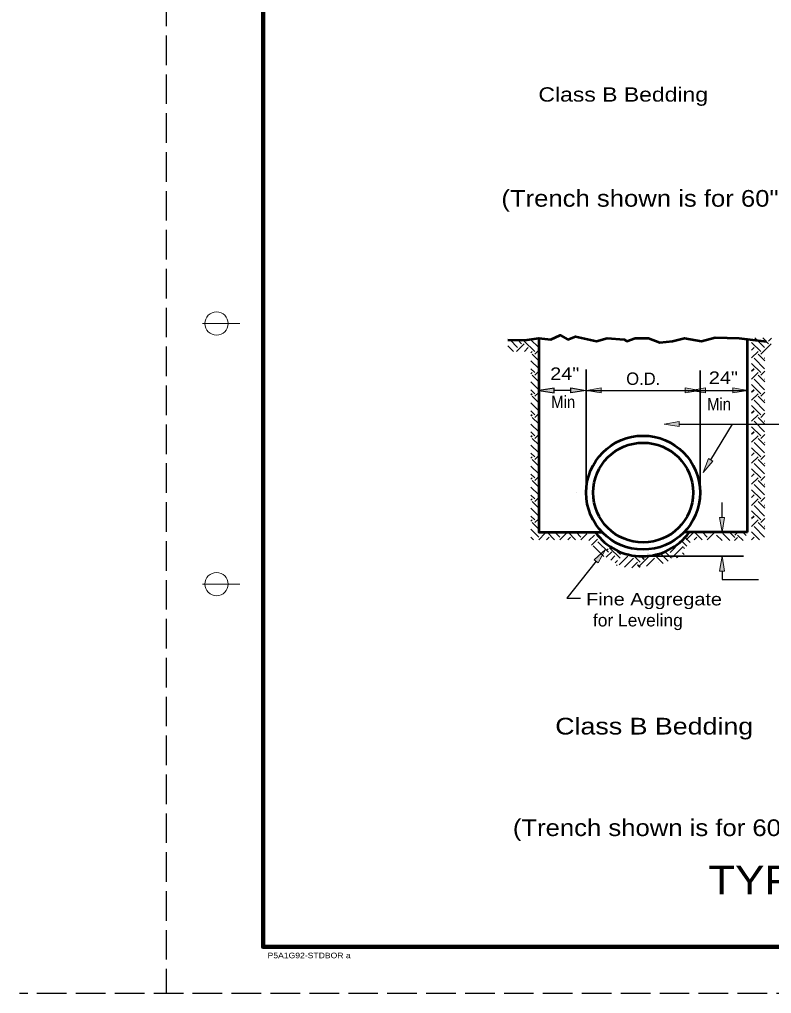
# Model space of a CAD drawing. Extents: x 36.1 to 71.5, y 0.2 to 22.2.
# Drawn here: x 36.14 to 44.21, y 0.21 to 10.68 of the extents above; entities that cross this region are included whole.
import ezdxf

# ---------------------------------------------------------------- set-up
doc = ezdxf.new("R2010")
doc.units = 0
doc.header["$LTSCALE"] = 0.053
doc.header["$PDMODE"] = 32
doc.header["$PDSIZE"] = 0.0265
doc.linetypes.add('LONG_DASHED', pattern=[7.5, 6, -1.5])
for name, color, linetype, lineweight in [('1', 7, 'Continuous', 35), ('3', 7, 'Continuous', 25), ('4', 7, 'Continuous', 35), ('6', 7, 'Continuous', 13)]:
    doc.layers.add(name, color=color, linetype=linetype, lineweight=lineweight)

msp = doc.modelspace()

# ---------------------------------------------------------------- hatches: boundary and pattern name
at = {"layer": '1'}
for points in [[(41.87908, 6.66708), (41.87908, 6.72042), (41.71908, 6.69375), (41.71908, 6.69375)], [(42.05908, 6.66875), (42.05908, 6.72208), (42.21908, 6.69542), (42.21908, 6.69542)], [(42.38567, 6.66733), (42.38567, 6.72075), (42.22567, 6.69408), (42.22567, 6.69408)], [(43.28842, 6.66733), (43.28842, 6.72075), (43.44842, 6.69408), (43.44842, 6.69408)]]:
    msp.add_hatch(color=256, dxfattribs=at).paths.add_polyline_path(points)
at = {"layer": '3'}
for points in [[(43.50392, 6.66858), (43.50392, 6.72192), (43.34392, 6.69525), (43.34392, 6.69525)], [(43.80058, 6.66858), (43.80058, 6.72192), (43.96058, 6.69525), (43.96058, 6.69525)], [(43.22292, 6.30617), (43.22292, 6.35942), (43.06292, 6.33283), (43.06292, 6.33283)], [(43.58492, 5.93458), (43.53925, 5.96217), (43.4795, 5.81133), (43.4795, 5.81133)], [(43.71075, 5.3305), (43.65742, 5.3305), (43.68408, 5.1705), (43.68408, 5.1705)], [(42.31042, 4.87483), (42.35225, 4.84158), (42.43058, 4.98367), (42.43058, 4.98367)], [(43.71075, 4.75192), (43.65742, 4.75192), (43.68408, 4.91192), (43.68408, 4.91192)]]:
    msp.add_hatch(color=256, dxfattribs=at).paths.add_polyline_path(points)

# ---------------------------------------------------------------- linework, layer by layer
at = {"layer": '1', "linetype": 'LONG_DASHED', "lineweight": 25}
for p, q in [((37.71217, 22.21317), (37.71217, 0.21317)), ((71.33717, 0.21317), (36.13717, 0.21317))]:
    msp.add_line(p, q, dxfattribs=at)
at = {"layer": '1', "lineweight": 158}
msp.add_line((38.75383, 21.71317), (38.75383, 0.71317), dxfattribs=at)
at = {"layer": '1', "lineweight": 13}
for p, q in [((38.50383, 7.41317), (38.10383, 7.41317)), ((43.61867, 5.1705), (43.45367, 5.1705)), ((38.50383, 4.61317), (38.10383, 4.61317))]:
    msp.add_line(p, q, dxfattribs=at)
at = {"layer": '1', "lineweight": 53}
for q in [(43.95658, 7.2445), (43.27125, 5.1705)]:
    msp.add_line((43.95658, 5.1705), q, dxfattribs=at)
at = {"layer": '1'}
for p, q in [((42.22408, 5.67058), (42.22408, 6.91892)), ((43.44833, 5.65942), (43.44833, 6.90775))]:
    msp.add_line(p, q, dxfattribs=at)
at = {"layer": '1', "lineweight": 25}
for p, q in [((42.06375, 6.69375), (41.88033, 6.69375)), ((42.2295, 6.69408), (43.44833, 6.69408))]:
    msp.add_line(p, q, dxfattribs=at)
at = {"layer": '1', "lineweight": 158}
msp.add_lwpolyline([(71.25383, 21.71317), (71.25383, 0.71317), (38.75383, 0.71317)], dxfattribs=at)
at = {"layer": '1', "lineweight": 53}
for points in [[(41.38342, 7.23725), (41.56667, 7.23458), (41.71408, 7.25475), (41.71408, 5.1705), (42.3945, 5.1705)], [(41.71408, 7.25475), (41.84458, 7.24108), (41.94267, 7.28867), (42.02575, 7.24108), (42.10892, 7.27275), (42.3355, 7.22517), (42.44892, 7.25683), (42.63025, 7.24108), (42.66042, 7.22517), (42.75108, 7.25683), (42.89467, 7.25683), (43.0155, 7.20925), (43.1515, 7.22517), (43.27992, 7.25683), (43.46125, 7.22517), (43.61083, 7.2615)], [(43.61083, 7.2615), (43.86717, 7.25475), (44.16192, 7.22117)]]:
    msp.add_lwpolyline(points, dxfattribs=at)
at = {"layer": '1', "lineweight": 25}
for points in [[(41.87908, 6.66708), (41.87908, 6.72042), (41.71908, 6.69375), (41.71908, 6.69375)], [(42.05908, 6.66875), (42.05908, 6.72208), (42.21908, 6.69542), (42.21908, 6.69542)]]:
    msp.add_lwpolyline(points, close=True, dxfattribs=at)
at = {"layer": '1', "lineweight": 13}
for points in [[(42.38567, 6.66733), (42.38567, 6.72075), (42.22567, 6.69408), (42.22567, 6.69408)], [(43.28842, 6.66733), (43.28842, 6.72075), (43.44842, 6.69408), (43.44842, 6.69408)]]:
    msp.add_lwpolyline(points, close=True, dxfattribs=at)
for centre in [(38.25383, 7.41317), (38.25383, 4.61317)]:
    msp.add_circle(centre, 0.125, dxfattribs=at)
at = {"layer": '1', "lineweight": 53}
for radius in [0.61202, 0.53646]:
    msp.add_circle((42.83535, 5.59617), radius, dxfattribs=at)
msp.add_arc((42.82617, 5.53271), 0.6208, 215.70389, 324.29611, dxfattribs=at)
at = {"layer": '1'}
msp.add_point((38.75383, 0.71317), dxfattribs=at)
at = {"layer": '3'}
for p, q in [((43.348, 6.69458), (43.95658, 6.69458)), ((43.22292, 6.33283), (44.53925, 6.33283)), ((43.56208, 5.94842), (43.79375, 6.33283)), ((43.68408, 5.3305), (43.68408, 5.4905)), ((43.68408, 4.75192), (43.68408, 4.661)), ((43.68408, 4.661), (44.07525, 4.661))]:
    msp.add_line(p, q, dxfattribs=at)
at = {"layer": '3', "lineweight": 13}
for p, q in [((43.61083, 6.68608), (43.61092, 6.68608)), ((43.68408, 4.91192), (43.68425, 4.91192))]:
    msp.add_line(p, q, dxfattribs=at)
at = {"layer": '3', "lineweight": 35}
msp.add_line((42.80025, 4.91192), (43.9145, 4.91192), dxfattribs=at)
at = {"layer": '3', "lineweight": 13}
for points in [[(43.50392, 6.66858), (43.50392, 6.72192), (43.34392, 6.69525), (43.34392, 6.69525)], [(43.80058, 6.66858), (43.80058, 6.72192), (43.96058, 6.69525), (43.96058, 6.69525)], [(43.22292, 6.30617), (43.22292, 6.35942), (43.06292, 6.33283), (43.06292, 6.33283)], [(43.58492, 5.93458), (43.53925, 5.96217), (43.4795, 5.81133), (43.4795, 5.81133)], [(43.71075, 5.3305), (43.65742, 5.3305), (43.68408, 5.1705), (43.68408, 5.1705)], [(42.31042, 4.87483), (42.35225, 4.84158), (42.43058, 4.98367), (42.43058, 4.98367)], [(43.71075, 4.75192), (43.65742, 4.75192), (43.68408, 4.91192), (43.68408, 4.91192)]]:
    msp.add_lwpolyline(points, close=True, dxfattribs=at)
at = {"layer": '3'}
msp.add_lwpolyline([(42.33133, 4.85817), (42.01775, 4.46167), (42.16392, 4.46167)], dxfattribs=at)
at = {"layer": '4'}
for p, q in [((41.48792, 7.15467), (41.40567, 7.23692)), ((41.53042, 7.197), (41.49175, 7.23567)), ((41.67183, 7.11217), (41.55867, 7.22525)), ((41.71408, 7.15483), (41.62617, 7.24267)), ((44.14025, 7.15467), (44.03442, 7.26058)), ((44.18275, 7.22525), (44.21325, 7.25592)), ((41.44425, 7.1135), (41.38342, 7.17442)), ((41.47517, 7.1135), (41.55867, 7.197)), ((41.56, 7.1135), (41.60108, 7.15467)), ((41.67183, 7.08392), (41.71408, 7.12608)), ((44.09792, 7.11217), (44.00033, 7.20958)), ((44.00033, 7.12792), (44.02717, 7.15467)), ((44.09792, 7.08392), (44.211, 7.197)), ((41.63075, 7.09942), (41.64358, 7.11217)), ((41.71408, 7.0135), (41.64358, 7.08392)), ((44.00033, 7.043), (44.06958, 7.11217)), ((44.14025, 6.92833), (44.02717, 7.0415)), ((44.14133, 7.01208), (44.06958, 7.08392)), ((44.14025, 7.0415), (44.14133, 7.04258)), ((41.71408, 6.9285), (41.63075, 7.01183)), ((41.67183, 6.886), (41.63075, 6.92708)), ((44.09792, 6.886), (44.00033, 6.98342)), ((44.00033, 6.90167), (44.02717, 6.92833)), ((41.63075, 6.87308), (41.64358, 6.886)), ((41.71408, 6.78717), (41.64358, 6.85758)), ((41.67183, 6.85758), (41.71408, 6.89983)), ((44.00033, 6.81675), (44.06958, 6.886)), ((44.14025, 6.70208), (44.02717, 6.81525)), ((44.14133, 6.78583), (44.06958, 6.85758)), ((44.09792, 6.85758), (44.14133, 6.90117)), ((41.71408, 6.70233), (41.63075, 6.78558)), ((41.67183, 6.65967), (41.63075, 6.70075)), ((44.09792, 6.65967), (44.00033, 6.75717)), ((44.00033, 6.67533), (44.02717, 6.70208)), ((41.63075, 6.64683), (41.64358, 6.65967)), ((41.71408, 6.56083), (41.64358, 6.63142)), ((41.67183, 6.63142), (41.71408, 6.67358)), ((44.00033, 6.5905), (44.06958, 6.65967)), ((44.14133, 6.55958), (44.06958, 6.63142)), ((44.09792, 6.63142), (44.14133, 6.67483)), ((41.71408, 6.47608), (41.63075, 6.55942)), ((44.09792, 6.43342), (44.00033, 6.53083)), ((44.14025, 6.47583), (44.02717, 6.58892)), ((44.14025, 6.58892), (44.14133, 6.59008)), ((41.67183, 6.43342), (41.63075, 6.4745)), ((41.63075, 6.42058), (41.64358, 6.43342)), ((41.71408, 6.33458), (41.64358, 6.40517)), ((41.67183, 6.40517), (41.71408, 6.44725)), ((44.00033, 6.44908), (44.02717, 6.47583)), ((44.00033, 6.36417), (44.06958, 6.43342)), ((44.14133, 6.33325), (44.06958, 6.40517)), ((44.09792, 6.40517), (44.14133, 6.44867)), ((41.71408, 6.24975), (41.63075, 6.333)), ((44.09792, 6.20717), (44.00033, 6.3045)), ((44.14025, 6.2495), (44.02717, 6.36267)), ((44.14025, 6.36267), (44.14133, 6.36375)), ((41.67183, 6.20717), (41.63075, 6.24817)), ((41.63075, 6.19425), (41.64358, 6.20717)), ((41.71408, 6.10825), (41.64358, 6.17883)), ((41.67183, 6.17883), (41.71408, 6.221)), ((44.00033, 6.22283), (44.02717, 6.2495)), ((44.00033, 6.13792), (44.06958, 6.20717)), ((44.14133, 6.107), (44.06958, 6.17883)), ((44.09792, 6.17883), (44.14133, 6.22242)), ((41.71408, 6.0235), (41.63075, 6.10683)), ((44.09792, 5.98083), (44.00033, 6.07833)), ((44.14025, 6.02325), (44.02717, 6.1365)), ((44.14025, 6.1365), (44.14133, 6.1375)), ((41.67183, 5.98083), (41.63075, 6.02183)), ((41.63075, 5.968), (41.64358, 5.98083)), ((41.67183, 5.9525), (41.71408, 5.99483)), ((44.00033, 5.9965), (44.02717, 6.02325)), ((44.00033, 5.91167), (44.06958, 5.98083)), ((44.09792, 5.9525), (44.14133, 5.99608)), ((41.71408, 5.79725), (41.63075, 5.8805)), ((41.71408, 5.88208), (41.64358, 5.9525)), ((44.14025, 5.797), (44.02717, 5.91008)), ((44.14133, 5.88075), (44.06958, 5.9525)), ((44.14025, 5.91008), (44.14133, 5.91125)), ((41.67183, 5.75458), (41.63075, 5.79567)), ((41.67183, 5.72633), (41.71408, 5.7685)), ((44.09792, 5.75458), (44.00033, 5.85192)), ((44.00033, 5.77025), (44.02717, 5.797)), ((44.09792, 5.72633), (44.14133, 5.76983)), ((41.63075, 5.74183), (41.64358, 5.75458)), ((41.71408, 5.57083), (41.63075, 5.65417)), ((41.71408, 5.65583), (41.64358, 5.72633)), ((44.00033, 5.6855), (44.06958, 5.75458)), ((44.14025, 5.57067), (44.02717, 5.68383)), ((44.14133, 5.65442), (44.06958, 5.72633)), ((44.14025, 5.68383), (44.14133, 5.68492)), ((41.67183, 5.52833), (41.63075, 5.56942)), ((44.09792, 5.52833), (44.00033, 5.62575)), ((44.00033, 5.544), (44.02717, 5.57067)), ((41.63075, 5.5155), (41.64358, 5.52833)), ((41.71408, 5.4295), (41.64358, 5.49992)), ((41.67183, 5.49992), (41.71408, 5.54217)), ((44.00033, 5.45917), (44.06958, 5.52833)), ((44.14025, 5.3445), (44.02717, 5.45758)), ((44.14133, 5.42817), (44.06958, 5.49992)), ((44.09792, 5.49992), (44.14133, 5.54358)), ((44.14025, 5.45758), (44.14133, 5.45867)), ((41.71408, 5.34467), (41.63075, 5.42792)), ((41.67183, 5.302), (41.63075, 5.34308)), ((44.09792, 5.302), (44.00033, 5.3995)), ((44.00033, 5.31767), (44.02717, 5.3445)), ((41.63075, 5.28917), (41.64358, 5.302)), ((41.71408, 5.20317), (41.64358, 5.27375)), ((41.67183, 5.27375), (41.71408, 5.31592)), ((44.00033, 5.23283), (44.06958, 5.302)), ((44.14133, 5.20192), (44.06958, 5.27375)), ((44.09792, 5.27375), (44.14133, 5.31725)), ((41.71425, 5.11817), (41.63075, 5.20175)), ((41.71417, 5.08983), (41.785, 5.1605)), ((41.88408, 5.08983), (41.80333, 5.1705)), ((41.94058, 5.11817), (41.88825, 5.1705)), ((41.94042, 5.08983), (42.01125, 5.1605)), ((42.16675, 5.11817), (42.1145, 5.1705)), ((42.16667, 5.08983), (42.2295, 5.1525)), ((42.25358, 5.08033), (42.31242, 5.13925)), ((43.29808, 5.08983), (43.36892, 5.1605)), ((43.468, 5.08983), (43.38725, 5.1705)), ((43.52442, 5.11817), (43.47217, 5.1705)), ((43.52425, 5.08983), (43.59517, 5.1605)), ((43.68358, 5.08017), (43.62308, 5.14075)), ((43.7685, 5.08017), (43.6905, 5.15817)), ((43.82108, 5.1125), (43.76617, 5.16742)), ((43.82108, 5.14075), (43.85492, 5.17458)), ((43.90992, 5.08017), (43.84933, 5.14075)), ((43.94042, 5.1345), (43.9125, 5.16258)), ((44.08375, 5.08983), (44.00033, 5.17317)), ((44.14025, 5.11817), (44.02717, 5.23125)), ((44.14025, 5.23125), (44.14133, 5.2325)), ((41.65775, 5.08983), (41.63075, 5.11683)), ((41.79892, 5.08983), (41.82733, 5.11817)), ((42.02525, 5.08983), (42.05367, 5.11817)), ((42.28258, 5.03208), (42.34617, 5.09567)), ((42.46217, 4.95533), (42.34908, 5.0685)), ((43.12525, 4.9535), (43.23833, 5.06667)), ((43.30525, 5.02042), (43.24625, 5.07942)), ((43.342, 5.059), (43.28975, 5.11133)), ((43.38292, 5.08983), (43.41133, 5.11817)), ((43.81708, 5.08017), (43.84933, 5.1125)), ((43.99875, 5.08983), (44.02717, 5.11817)), ((42.41208, 4.91092), (42.29892, 5.02408)), ((42.4395, 4.90258), (42.49808, 4.96108)), ((42.44883, 4.97975), (42.46117, 4.99208)), ((42.58833, 4.8915), (42.47525, 5.00458)), ((42.59267, 4.93), (42.5575, 4.96525)), ((43.05142, 4.83317), (42.96092, 4.92383)), ((43.10433, 4.86133), (43.02258, 4.94317)), ((43.14092, 4.8905), (43.07158, 4.95983)), ((43.1505, 4.90342), (43.26375, 5.01658)), ((43.27467, 4.93258), (43.25933, 4.94775)), ((43.27992, 4.99492), (43.2675, 5.00742)), ((42.48817, 4.87192), (42.53283, 4.91658)), ((42.53575, 4.84042), (42.56192, 4.86667)), ((42.55717, 4.81275), (42.54858, 4.82117)), ((42.57692, 4.82117), (42.66983, 4.91408)), ((42.63675, 4.79608), (42.73258, 4.89183)), ((42.715, 4.7895), (42.77492, 4.8495)), ((42.80325, 4.8495), (42.74042, 4.91233)), ((42.80258, 4.7935), (42.77492, 4.82117)), ((42.78608, 4.80017), (42.89908, 4.91333)), ((42.8475, 4.8785), (42.81983, 4.90633)), ((42.87192, 4.805), (42.95875, 4.89183)), ((42.99942, 4.84767), (43.00125, 4.8495)), ((43.20625, 4.89692), (43.19217, 4.91108))]:
    msp.add_line(p, q, dxfattribs=at)
at = {"layer": '4', "lineweight": 13}
for p, q in [((41.53042, 7.22525), (41.54, 7.235)), ((41.71408, 7.23967), (41.70083, 7.25292)), ((44.18275, 7.197), (44.12158, 7.25825)), ((44.14025, 6.81525), (44.14133, 6.81633)), ((43.32458, 6.69017), (43.32475, 6.69017)), ((43.32458, 6.67817), (43.32475, 6.67817)), ((41.75658, 5.1605), (41.74683, 5.1705)), ((41.98292, 5.1605), (41.97308, 5.1705)), ((42.11033, 5.08983), (42.02967, 5.1705)), ((42.20925, 5.1605), (42.19942, 5.1705)), ((43.34058, 5.1605), (43.33067, 5.1705)), ((43.56692, 5.1605), (43.55692, 5.1705)), ((43.75067, 5.08983), (43.75183, 5.091)), ((42.39308, 5.005), (42.39325, 5.00517)), ((42.888, 4.93433), (42.8875, 4.93492))]:
    msp.add_line(p, q, dxfattribs=at)
at = {"layer": '6', "lineweight": 25}
for p, q in [((41.79792, 6.70175), (41.798, 6.70175)), ((41.79792, 6.69375), (41.798, 6.69375)), ((42.20783, 6.69375), (42.20792, 6.69375))]:
    msp.add_line(p, q, dxfattribs=at)
at = {"layer": '6'}
for p, q in [((43.348, 6.69408), (43.34808, 6.69408)), ((42.12392, 5.59617), (42.124, 5.59617)), ((43.348, 5.59617), (43.34808, 5.59617)), ((43.69867, 5.1705), (43.69883, 5.1705)), ((42.72025, 4.91192), (42.72033, 4.91192))]:
    msp.add_line(p, q, dxfattribs=at)

# ---------------------------------------------------------------- texts
at = {"layer": '1'}
msp.add_text('O.D.', height=0.133, dxfattribs=at).set_placement((42.65375, 6.75408))
at = {"layer": '1', "width": 1.15}
msp.add_text('P5A1G92-STDBOR a', height=0.06, dxfattribs=at).set_placement((38.80183, 0.59217))
at = {"layer": '3'}
for s, height, width, p in [('Class B Bedding', 0.1536, 1.2, (41.71075, 9.79833)), ('(Trench shown is for 60" thru 108" flexible', 0.1792, 1.15, (41.313, 8.66908)), ('24"', 0.133, 1.2, (41.83717, 6.80808)), ('24"', 0.133, 1.2, (43.54117, 6.76508)), ('Min', 0.133, 0.9, (41.84767, 6.50417)), ('Min', 0.133, 0.9, (43.52225, 6.48025)), ('Fine Aggregate', 0.133, 1.2, (42.22292, 4.38417)), ('for Leveling', 0.133, 1.05, (42.29625, 4.15808)), ('Class B Bedding', 0.1792, 1.2, (41.89158, 2.99675)), ('(Trench shown is for 60" thru 108" rigid', 0.1792, 1.15, (41.43617, 1.9055)), ('TYPICAL PIPE BEDDING', 0.3072, 1.15, (43.53475, 1.27883))]:
    msp.add_text(s, height=height, dxfattribs=dict(at, width=width)).set_placement(p)

doc.saveas('drawing.dxf')
